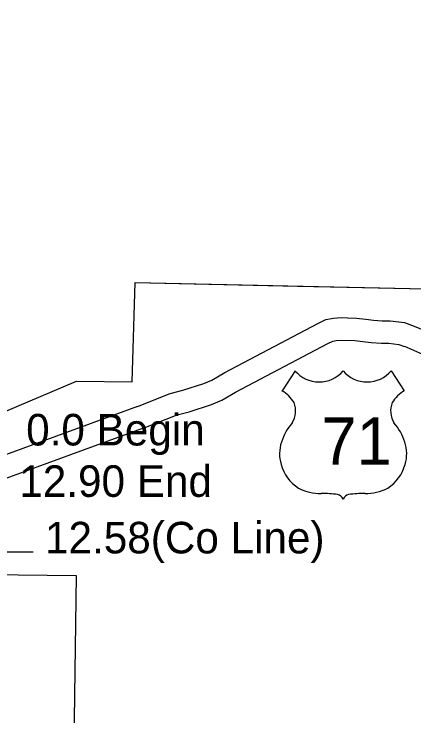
# Model space of a CAD drawing. Extents: x -939622 to -934245, y 1383184 to 1385301.
# Drawn here: x -936356.71 to -936340.67, y 1384400.3 to 1384428.48 of the extents above; entities that cross this region are included whole.
import ezdxf

# ---------------------------------------------------------------- set-up
doc = ezdxf.new("R2010")
doc.units = 0
for name, color, linetype in [('Level 15', 7, 'Continuous'), ('Level 2', 7, 'Continuous'), ('Level 22', 7, 'Continuous'), ('Level 25', 7, 'Continuous')]:
    doc.layers.add(name, color=color, linetype=linetype)

msp = doc.modelspace()

# ---------------------------------------------------------------- linework, layer by layer
at = {"layer": 'Level 15'}
for points in [[(-936351.753, 1384412.726), (-936350.447, 1384413.236), (-936349.942, 1384413.373), (-936349.096, 1384413.649), (-936348.771, 1384413.781), (-936348.26, 1384414.083), (-936344.529, 1384416.057), (-936344.205, 1384416.213), (-936343.897, 1384416.266), (-936343.573, 1384416.29), (-936343.341, 1384416.282)], [(-936343.319, 1384416.281), (-936342.97, 1384416.269), (-936342.607, 1384416.228), (-936342.298, 1384416.184), (-936341.943, 1384416.162), (-936341.622, 1384416.162), (-936341.053, 1384416.097), (-936340.663, 1384415.939), (-936339.97, 1384415.659)], [(-936351.426, 1384411.888), (-936350.165, 1384412.38), (-936349.684, 1384412.511), (-936348.786, 1384412.803), (-936348.37, 1384412.972), (-936347.821, 1384413.298), (-936344.123, 1384415.253), (-936343.928, 1384415.348), (-936343.788, 1384415.371), (-936343.555, 1384415.389), (-936343.037, 1384415.371), (-936342.722, 1384415.335), (-936342.389, 1384415.288), (-936341.971, 1384415.262), (-936341.674, 1384415.262), (-936341.277, 1384415.216), (-936341.054, 1384415.126)], [(-936341.05, 1384415.136), (-936339.48, 1384414.449)], [(-936363.962, 1384409.664), (-936363.087, 1384409.644), (-936362.362, 1384409.635), (-936361.646, 1384409.493), (-936361.203, 1384409.417), (-936360.984, 1384409.396), (-936360.556, 1384409.508), (-936351.744, 1384412.73)], [(-936363.982, 1384408.764), (-936363.103, 1384408.745), (-936362.456, 1384408.736), (-936361.809, 1384408.608), (-936361.322, 1384408.524), (-936360.911, 1384408.485), (-936360.287, 1384408.647), (-936351.435, 1384411.885)]]:
    msp.add_lwpolyline(points, dxfattribs=at)
at = {"layer": 'Level 2'}
for points in [[(-936357.586, 1384412.304), (-936354.205, 1384413.743), (-936351.973, 1384413.712), (-936351.848, 1384417.693), (-936339.598, 1384417.434), (-936339.533, 1384421.453), (-936333.441, 1384421.326), (-936333.337, 1384423.299), (-936331.389, 1384423.287), (-936331.362, 1384425.199), (-936323.21, 1384425.157), (-936323.154, 1384429.182), (-936314.965, 1384429.11), (-936314.714, 1384443.093)], [(-936343.366, 1384417.513), (-936339.598, 1384417.434), (-936339.533, 1384421.453), (-936333.441, 1384421.326), (-936333.337, 1384423.299), (-936331.389, 1384423.287), (-936331.362, 1384425.199), (-936323.21, 1384425.157), (-936323.154, 1384429.182), (-936314.965, 1384429.11)], [(-936357.586, 1384412.304), (-936354.205, 1384413.743), (-936351.973, 1384413.712), (-936351.848, 1384417.693), (-936345.347, 1384417.555), (-936343.366, 1384417.513)], [(-936354.499, 1384387.27), (-936354.41, 1384391.534), (-936354.205, 1384405.921), (-936357.731, 1384405.958), (-936357.73, 1384406.03)], [(-936354.499, 1384387.266), (-936354.41, 1384391.534), (-936354.205, 1384405.921), (-936357.731, 1384405.958), (-936357.73, 1384406.03)]]:
    msp.add_lwpolyline(points, dxfattribs=at)
at = {"layer": 'Level 22'}
for p, q in [((-936345.441, 1384414.155), (-936345.961, 1384413.352)), ((-936341.581, 1384414.155), (-936341.062, 1384413.352))]:
    msp.add_line(p, q, dxfattribs=at)
for centre, radius, start, end in [((-936344.475, 1384414.968), 1.264, 220.075, 319.6701), ((-936342.548, 1384414.968), 1.264, 220.3299, 319.925), ((-936346.639, 1384412.186), 1.349, 30.7809, 59.9883), ((-936340.383, 1384412.186), 1.349, 120.0117, 149.2191), ((-936346.342, 1384412.542), 0.925, 328.8105, 21.2108), ((-936340.68, 1384412.542), 0.925, 158.7892, 211.1895), ((-936343.924, 1384410.646), 2.157, 138.9565, 162.6913), ((-936343.098, 1384410.646), 2.157, 17.3087, 41.0435), ((-936344.636, 1384410.823), 1.426, 160.9576, 197.3819), ((-936342.386, 1384410.823), 1.426, 342.6181, 19.0424), ((-936344.404, 1384410.827), 1.65, 195.1074, 237.1312), ((-936342.618, 1384410.827), 1.65, 302.8688, 344.8926), ((-936344.373, 1384411.346), 2.118, 244.0771, 269.5779), ((-936342.649, 1384411.346), 2.118, 270.4221, 295.9229), ((-936344.324, 1384405.349), 3.88, 81.1942, 90.9539), ((-936343.839, 1384408.828), 0.372, 28.0342, 72.9864), ((-936343.183, 1384408.828), 0.372, 107.0136, 151.9658), ((-936342.698, 1384405.349), 3.88, 89.0461, 98.8058)]:
    msp.add_arc(centre, radius, start, end, dxfattribs=at)
at = {"layer": 'Level 25'}
msp.add_line((-936363.926, 1384406.891), (-936355.948, 1384406.891), dxfattribs=at)

# ---------------------------------------------------------------- texts
at = {"layer": 'Level 22'}
msp.add_text('71', height=1.9008, dxfattribs=at).set_placement((-936344.383, 1384410.382))
at = {"layer": 'Level 25'}
for s, p in [('0.0 Begin', (-936356.223, 1384411.155)), ('12.90 End', (-936356.498, 1384409.092)), ('12.58(Co Line)', (-936355.466, 1384406.822))]:
    msp.add_text(s, height=1.2672, dxfattribs=at).set_placement(p)

doc.saveas('drawing.dxf')
